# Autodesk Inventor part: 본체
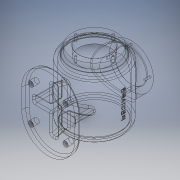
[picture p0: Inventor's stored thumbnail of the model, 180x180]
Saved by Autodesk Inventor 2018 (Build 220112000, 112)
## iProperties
Created: 2023-01
Part Number: 본체
Material: 일반
Document SubType Name: Modeling
Designer: home
Density: 1 g/cm^3
Appearance: 기본값
Author: home
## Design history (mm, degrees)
sketch "스케치1"
  geometry: L1 (0, 17)-(0, -17); L2 (-46, 17)-(-46, -17); L3 (46, -17)-(46, 17); C1 r 4.5 at (30, -30); C2 r 4.5 at (30, 30); C3 r 4.5 at (-30, 30); C4 r 4.5 at (-30, -30); A1 r 46 centre (0, 17) between (46, 17) and (-46, 17); A2 r 46 centre (0, -17) between (-46, -17) and (46, -17); 3 further points
  constraints: 8 end point, 6 centre point, 6 point on circle, 4 tangent, 1 equal radius, 1 midpoint, 1 parallel, 1 vertical
  dimensions: "d7" = 9 diameter of C2; "d8" = 9 diameter of C3; "d9" = 9 diameter of C4; "d18" = 60 distance of C1.centre C2.centre (derived); "d19" = 60 distance of C3.centre C2.centre (derived); "d22" = 92 distance between parallel lines of L2 L3; "d23" = 126 distance of point (0, -63) point (0, 63); "d140" = 16 distance from line of C2.centre L3; "d141" = 16 distance from line of C1.centre L3; "d142" = 76 distance from line of C3.centre L3; "d143" = 76 distance from line of C4.centre L3; "d144" = 42.42641 distance of C2.centre point (0, 0); "d145" = 42.42641 distance of C1.centre point (0, 0); "d146" = 42.42641 distance of C3.centre point (0, 0); "d147" = 42.42641 distance of C4.centre point (0, 0)
extrude "돌출1" new body sketch "스케치1" distance "d24" = 10; taper "d25" = 0 deg
node "작업 평면1"
sketch "스케치3"
  geometry: L1 (-27, 63)-(-38, 63); L2 (-38, 63)-(-38, 51); L3 (-38, 51)-(-50, 51); L4 (-27, 63)-(-27, 46); L5 (0, 0)-(0, 63); L6 (-50, 51)-(-50, -48.087); L7 (-45, -44.83)-(-45, 46); L8 (-45, 46)-(-27, 46); L9 (0, -59)-(0, -54); A1 r 120 centre (0, 61) between (-50, -48.087) and (0, -59); A2 r 115 centre (0, 61) between (-45, -44.83) and (0, -54)
  constraints: 18 end point, 5 vertical, 4 point on circle, 3 horizontal, 2 centre point, 1 other
  dimensions: "d30" = 38 distance of L5.end L1.end; "d31" = 12 distance of L1.end L2.end; "d34" = 17 distance of L1.start L4.end; "d55" = 120 radius of A1; "d56" = 122 distance from line of L9.start L1; "d58" = 59 distance of L9.start L5.start; "d59" = 100 diameter of L6 L5; "d60" = 5 radial gap between concentric circles of A1 A2; "d61" = 51 vertical distance of L5.start L2.end; "d62" = 54 diameter of L4 L5; "d63" = 76 diameter of L2 L5; "d64" = 0 distance from line of A1.centre L5
revolve "회전1" sketch "스케치3" stored, may be unused: angle "d65" = 90 deg
sketch "스케치4"
  geometry: L1 (-35, -5)-(0, -5); L2 (0, -5)-(35, -5); L3 (-35, 5)-(0, 5); L4 (0, 5)-(35, 5); L5 (-35, -5)-(-35, 5); L6 (35, -5)-(35, 5); 1 further point
  constraints: 12 end point, 2 vertical, 1 horizontal, 1 parallel
  dimensions: "d132" = 90 deg angle of L6 L3; "d133" = 90 deg angle of L6 L1; "d134" = 70 distance between parallel lines of L6 L5; "d135" = 10 distance between parallel lines of L2 L4; "d136" = 35 distance from line of point (0, 0) L6; "d137" = 5 distance from line of point (0, 0) L4; "d138" = 35 distance from line of L3.end L6; "d139" = 35 distance from line of L1.end L6
extrude "돌출2" join sketch "스케치4" stored distance "d70" = 10; taper "d71" = 0 deg
sketch "스케치5"
  geometry: L1 (10, 34.5)-(10, 25.5) reference; L2 (0, 17)-(0, 17) reference; L3 (0, 17)-(10, 17) reference; L4 (10, 17)-(10, 17) reference; L5 (0, 17)-(10, 17) reference; L6 (10, 40)-(30, 34.641); L7 (10, -17)-(10, 17) reference; L8 (10, -40)-(30, -34.641); L9 (10, -63)-(10, -17) reference; L10 (10, 17)-(10, 63) reference; L11 (30, -48.087)-(30, 51) reference; 1 further point
  constraints: 4 end point, 2 point on line
  dimensions: "d74" = 105 deg angle of L9 L8; "d75" = 23 distance of L10.end L6.start; "d76" = 80 distance of L8.start L6.start; "d77" = 105 deg angle of L10 L6; "d78" = 15.80156 distance from line of L11.end L6; "d79" = 82.72287 distance from line of L11.end L8
  node "투영된 루프1"
feature "리브1" dims "d80" = 1, "d81" = 10, "d82" = 0, "d83" = 0, "d84" = 1, "d85" = 1
feature "리브2" dims "d86" = 1, "d87" = 10, "d88" = 0, "d89" = 0, "d90" = 1, "d91" = 1
node "작업 평면2"
sketch "스케치6"
  geometry: L1 (38, 63)-(-38, 63) reference; C1 r 38 at (0, 0); 1 further point
  constraints: 1 centre point, 1 coincident
  dimensions: "d93" = 76 diameter of C1; "d94" = 63 distance from line of L1 point (0, 0) (derived)
extrude "돌출3" join sketch "스케치6" stored distance "d95" = 10; taper "d96" = 0 deg
sketch "스케치7"
  geometry: C1 r 27 at (0, 0); 1 further point
  constraints: 1 centre point, 1 coincident
  dimensions: "d97" = 54 diameter of C1
extrude "돌출4" cut sketch "스케치7" stored distance "d98" = 10; taper "d99" = 0 deg; dims "d30" = 38, "d31" = 12, "d34" = 17, "d55" = 120, "d56" = 122, "d58" = 59, "d59" = 100, "d60" = 5, "d61" = 51, "d62" = 54, "d63" = 76, "d64" = 0
sketch "스케치8" dims "d100" = 65
  geometry: L1 (-32.5, 0)-(0, 0); 1 further point
  constraints: 2 end point, 1 coincident, 1 horizontal, 1 horizontal alignment, 2 other
hole "구멍1" sketch "스케치8" at (-32.5, 0) diameter "d101" = 3.242; stored, may be unused: countersink angle "d105" = 90 deg, drill point angle "d107" = 118 deg; dims "d102" = 8, "d103" = 4, "d104" = 2, "d106" = 10
sketch "스케치9" dims "d111" = 65
  geometry: L1 (0, 0)-(0, 32.5); C1 r 38 at (0, 0) reference; C2 r 27 at (0, 0) reference; 1 further point
  constraints: 2 end point, 1 coincident, 1 vertical, 1 vertical alignment, 2 other
hole "구멍2" sketch "스케치9" at (0, 32.5) diameter "d112" = 3.242; stored, may be unused: countersink angle "d116" = 90 deg, drill point angle "d118" = 118 deg; dims "d113" = 8, "d114" = 4, "d115" = 2, "d117" = 10
chamfer "모따기1" distance "d122" = 1; stored, may be unused: second distance "d123" = 2, angle "d124" = 45 deg
fillet "모깎기1" dims "d125" = 8, "d126" = 3
node "작업 평면3"
sketch "스케치10" dims "d19" = 60 (derived)
  geometry: L1 (118, 63)-(42, 63) reference; L2 (0, -63)-(0, -17) reference; 3 further points
  constraints: 2 coincident, 1 other
  dimensions: "d128" = 63 distance from line of point (80, 0) L1; "d129" = 80 distance from line of L2 point (80, 0)
feature "엠보싱1" sketch "스케치10" dims "d7" = 9, "d8" = 9, "d9" = 9, "d18" = 60 (derived), "d19" = 60 (derived), "d22" = 92, "d23" = 126, "d130" = 0.5, "d131" = 0, "d140" = 16, "d141" = 16, "d142" = 76, "d143" = 76, "d144" = 42.42641, "d145" = 42.42641, "d146" = 42.42641, "d147" = 42.42641
node "솔리드1"
pattern_circular "원형 패턴1" dims angle "d109" = 360 deg
pattern_circular "원형 패턴2" dims angle "d120" = 360 deg
node "투영된 루프2"
other parameters: "d92" = -144, "d127" = 119
